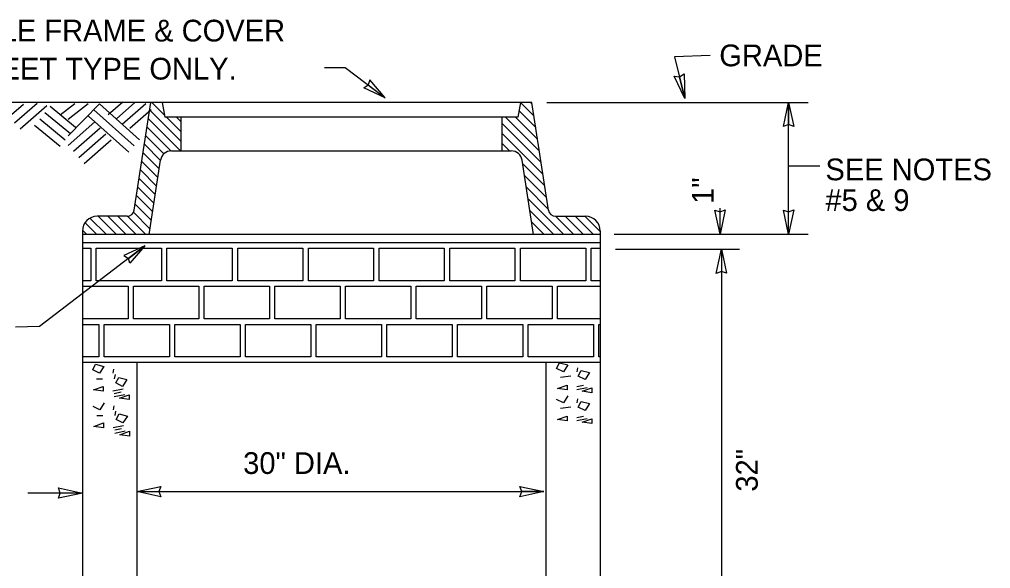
# Model space of a CAD drawing. Extents: x 19188 to 19495, y 20866 to 21061.
# Drawn here: x 19440.07 to 19477.48, y 21039.63 to 21060.79 of the extents above; entities that cross this region are included whole.
import ezdxf

# ---------------------------------------------------------------- set-up
doc = ezdxf.new("R2010")
doc.units = 0
doc.layers.add('G-ANNO-NOTE', color=7, linetype='Continuous')

msp = doc.modelspace()

# ---------------------------------------------------------------- linework, layer by layer
at = {"layer": 'G-ANNO-NOTE'}
for p, q in [((19466.687, 21059.399), (19465.308, 21059.346)), ((19465.308, 21059.346), (19465.711, 21057.746)), ((19451.822, 21058.933), (19452.62, 21058.933)), ((19452.62, 21058.933), (19454.162, 21057.763)), ((19465.711, 21057.746), (19465.503, 21058.573)), ((19445.138, 21057.586), (19431.945, 21057.586)), ((19440.235, 21057.514), (19439.682, 21057.029)), ((19440.75, 21057.549), (19439.889, 21056.793)), ((19441.13, 21057.464), (19440.096, 21056.557)), ((19442.233, 21056.626), (19441.256, 21057.426)), ((19441.64, 21057.106), (19442.212, 21057.549)), ((19441.946, 21056.946), (19442.724, 21057.548)), ((19443.152, 21057.532), (19441.946, 21056.305)), ((19443.152, 21057.532), (19444.704, 21056.145)), ((19444.057, 21057.597), (19443.497, 21057.105)), ((19444.506, 21057.572), (19443.819, 21056.97)), ((19444.946, 21057.54), (19444.028, 21056.735)), ((19444.497, 21053.442), (19445.138, 21057.586)), ((19459.81, 21057.586), (19445.138, 21057.586)), ((19445.179, 21057.585), (19445.654, 21057.11)), ((19445.565, 21057.587), (19445.674, 21057.02)), ((19459.378, 21057.583), (19459.274, 21057.02)), ((19459.377, 21057.584), (19459.89, 21057.071)), ((19459.755, 21057.585), (19459.82, 21057.52)), ((19460.451, 21053.442), (19459.81, 21057.586)), ((19460.394, 21057.586), (19470.452, 21057.586)), ((19469.705, 21052.518), (19469.705, 21057.586)), ((19469.705, 21057.586), (19469.705, 21056.733)), ((19442.034, 21056.383), (19441.057, 21057.183)), ((19442.734, 21057.064), (19444.286, 21055.677)), ((19442.943, 21057.298), (19444.495, 21055.912)), ((19445.153, 21057.303), (19444.327, 21056.579)), ((19445.092, 21057.292), (19446.292, 21056.092)), ((19459.274, 21057.02), (19445.674, 21057.02)), ((19445.744, 21057.021), (19446.292, 21056.472)), ((19446.12, 21057.023), (19446.292, 21056.852)), ((19446.292, 21057.025), (19446.292, 21055.729)), ((19458.656, 21057.025), (19458.656, 21055.729)), ((19458.797, 21057.024), (19460.098, 21055.723)), ((19459.18, 21057.021), (19460.029, 21056.172)), ((19459.32, 21057.261), (19459.96, 21056.621)), ((19441.636, 21055.896), (19440.659, 21056.696)), ((19441.835, 21056.139), (19440.858, 21056.94)), ((19442.98, 21056.839), (19441.946, 21055.932)), ((19444.991, 21056.634), (19445.914, 21055.71)), ((19445.042, 21056.963), (19446.275, 21055.729)), ((19458.656, 21056.785), (19460.168, 21055.273)), ((19443.187, 21056.603), (19442.153, 21055.696)), ((19443.395, 21056.366), (19442.36, 21055.46)), ((19444.94, 21056.304), (19445.63, 21055.615)), ((19458.656, 21056.405), (19460.238, 21054.823)), ((19443.602, 21056.13), (19442.567, 21055.223)), ((19444.889, 21055.976), (19445.508, 21055.356)), ((19458.656, 21056.025), (19458.956, 21055.725)), ((19444.838, 21055.647), (19445.457, 21055.027)), ((19445.929, 21055.724), (19459.019, 21055.724)), ((19444.787, 21055.318), (19445.407, 21054.698)), ((19445.066, 21052.499), (19445.51, 21055.364)), ((19459.882, 21052.499), (19459.438, 21055.364)), ((19459.461, 21055.22), (19460.307, 21054.374)), ((19470.912, 21055.132), (19469.705, 21055.132)), ((19444.736, 21054.989), (19445.356, 21054.369)), ((19459.53, 21054.771), (19460.376, 21053.925)), ((19444.685, 21054.66), (19445.305, 21054.04)), ((19444.583, 21054.002), (19445.203, 21053.382)), ((19444.634, 21054.331), (19445.254, 21053.711)), ((19459.6, 21054.322), (19460.446, 21053.475)), ((19444.533, 21053.673), (19445.152, 21053.053)), ((19459.669, 21053.872), (19461.044, 21052.497)), ((19444.462, 21053.363), (19445.101, 21052.724)), ((19459.739, 21053.423), (19460.663, 21052.498)), ((19467.061, 21052.518), (19467.061, 21053.516)), ((19467.061, 21052.518), (19467.061, 21053.371)), ((19469.705, 21052.518), (19469.705, 21053.371)), ((19442.599, 21052.946), (19443.049, 21052.496)), ((19442.801, 21053.124), (19443.429, 21052.497)), ((19444.217, 21053.203), (19443.065, 21053.203)), ((19443.103, 21053.203), (19443.808, 21052.497)), ((19443.483, 21053.203), (19444.187, 21052.498)), ((19443.863, 21053.203), (19444.567, 21052.499)), ((19444.244, 21053.201), (19444.946, 21052.499)), ((19459.808, 21052.973), (19460.283, 21052.499)), ((19460.717, 21053.204), (19461.424, 21052.497)), ((19460.731, 21053.203), (19461.883, 21053.203)), ((19461.099, 21053.203), (19461.805, 21052.496)), ((19461.479, 21053.203), (19462.185, 21052.496)), ((19461.859, 21053.203), (19462.449, 21052.612)), ((19442.498, 21052.668), (19442.67, 21052.496)), ((19442.5, 21052.637), (19442.5, 21052.496)), ((19442.5, 21052.508), (19442.511, 21052.496)), ((19462.449, 21052.496), (19442.5, 21052.496)), ((19442.5, 21052.496), (19442.5, 21034.451)), ((19459.878, 21052.524), (19459.903, 21052.499)), ((19462.449, 21052.508), (19462.437, 21052.496)), ((19462.449, 21052.637), (19462.449, 21052.496)), ((19462.449, 21052.496), (19462.449, 21034.451)), ((19462.981, 21052.518), (19470.452, 21052.518)), ((19462.449, 21052.181), (19442.5, 21052.181)), ((19463.038, 21051.931), (19467.808, 21051.931)), ((19467.119, 21051.931), (19467.119, 21034.434)), ((19467.119, 21051.931), (19467.119, 21051.079)), ((19462.449, 21047.573), (19442.5, 21047.573)), ((19442.894, 21047.29), (19443.009, 21047.503)), ((19443.152, 21047.156), (19442.894, 21047.29)), ((19443.009, 21047.503), (19443.325, 21047.423)), ((19443.325, 21047.423), (19443.152, 21047.156)), ((19443.698, 21047.316), (19443.67, 21047.156)), ((19444.594, 21047.573), (19444.594, 21034.451)), ((19460.354, 21047.573), (19460.354, 21034.451)), ((19460.768, 21047.343), (19460.883, 21047.556)), ((19461.026, 21047.209), (19460.768, 21047.343)), ((19460.883, 21047.556), (19461.199, 21047.476)), ((19461.199, 21047.476), (19461.026, 21047.209)), ((19461.572, 21047.37), (19461.544, 21047.209)), ((19461.601, 21047.049), (19461.716, 21047.263)), ((19461.716, 21047.263), (19462.032, 21047.183)), ((19443.037, 21046.943), (19443.267, 21046.943)), ((19443.756, 21047.103), (19443.727, 21046.943)), ((19443.785, 21046.783), (19443.899, 21046.996)), ((19443.899, 21046.996), (19444.216, 21046.916)), ((19444.216, 21046.916), (19444.043, 21046.65)), ((19461.314, 21047.049), (19460.912, 21046.996)), ((19461.86, 21046.916), (19461.601, 21047.049)), ((19462.032, 21047.183), (19461.86, 21046.916)), ((19442.923, 21046.516), (19443.296, 21046.65)), ((19443.296, 21046.462), (19442.923, 21046.516)), ((19443.296, 21046.65), (19443.296, 21046.462)), ((19444.072, 21046.543), (19443.67, 21046.462)), ((19444.043, 21046.65), (19443.785, 21046.783)), ((19460.797, 21046.57), (19461.17, 21046.703)), ((19461.17, 21046.516), (19460.797, 21046.57)), ((19461.17, 21046.703), (19461.17, 21046.516)), ((19461.544, 21046.65), (19461.802, 21046.703)), ((19461.946, 21046.596), (19461.544, 21046.516)), ((19461.745, 21046.462), (19462.119, 21046.596)), ((19462.119, 21046.596), (19462.119, 21046.409)), ((19443.727, 21046.383), (19443.986, 21046.436)), ((19444.129, 21046.329), (19443.727, 21046.249)), ((19443.928, 21046.196), (19444.302, 21046.329)), ((19444.302, 21046.142), (19443.928, 21046.196)), ((19444.302, 21046.329), (19444.302, 21046.142)), ((19461.026, 21046.015), (19460.768, 21046.149)), ((19461.199, 21046.282), (19461.026, 21046.015)), ((19461.572, 21046.175), (19461.544, 21046.015)), ((19462.119, 21046.409), (19461.745, 21046.462)), ((19443.167, 21045.747), (19442.909, 21045.881)), ((19443.34, 21046.014), (19443.167, 21045.747)), ((19443.713, 21045.908), (19443.685, 21045.747)), ((19461.314, 21045.855), (19460.912, 21045.802)), ((19461.601, 21045.855), (19461.716, 21046.069)), ((19461.86, 21045.722), (19461.601, 21045.855)), ((19461.716, 21046.069), (19462.032, 21045.989)), ((19462.032, 21045.989), (19461.86, 21045.722)), ((19443.053, 21045.534), (19443.282, 21045.534)), ((19443.771, 21045.694), (19443.742, 21045.534)), ((19443.8, 21045.374), (19443.915, 21045.588)), ((19443.915, 21045.588), (19444.231, 21045.508)), ((19444.231, 21045.508), (19444.058, 21045.241)), ((19460.797, 21045.375), (19461.17, 21045.508)), ((19461.17, 21045.508), (19461.17, 21045.322)), ((19461.544, 21045.455), (19461.802, 21045.508)), ((19461.946, 21045.402), (19461.544, 21045.322)), ((19461.745, 21045.269), (19462.119, 21045.402)), ((19462.119, 21045.402), (19462.119, 21045.215)), ((19442.937, 21045.107), (19443.311, 21045.241)), ((19443.311, 21045.054), (19442.937, 21045.107)), ((19443.311, 21045.241), (19443.311, 21045.054)), ((19444.087, 21045.134), (19443.685, 21045.054)), ((19443.742, 21044.974), (19444.001, 21045.027)), ((19444.058, 21045.241), (19443.8, 21045.374)), ((19461.17, 21045.322), (19460.797, 21045.375)), ((19462.119, 21045.215), (19461.745, 21045.269)), ((19444.144, 21044.921), (19443.742, 21044.841)), ((19443.944, 21044.788), (19444.317, 21044.921)), ((19444.317, 21044.734), (19443.944, 21044.788)), ((19444.317, 21044.921), (19444.317, 21044.734)), ((19442.5, 21042.542), (19440.394, 21042.542)), ((19442.5, 21042.542), (19441.646, 21042.542)), ((19444.594, 21042.596), (19460.279, 21042.596)), ((19444.594, 21042.596), (19445.447, 21042.596)), ((19460.279, 21042.596), (19459.427, 21042.596))]:
    msp.add_line(p, q, dxfattribs=at)
for points in [[(19465.503, 21058.573), (19465.682, 21058.695), (19465.711, 21057.746), (19465.296, 21058.596), (19465.503, 21058.573)], [(19469.705, 21056.733), (19469.501, 21056.658), (19469.705, 21057.586), (19469.9, 21056.66), (19469.705, 21056.733)], [(19467.061, 21053.371), (19467.265, 21053.446), (19467.061, 21052.518), (19466.867, 21053.444), (19467.061, 21053.371)], [(19469.705, 21053.371), (19469.909, 21053.446), (19469.705, 21052.518), (19469.51, 21053.444), (19469.705, 21053.371)], [(19444.907, 21052.068), (19440.852, 21048.956), (19439.916, 21048.938)], [(19442.5, 21051.972), (19442.825, 21051.972), (19442.825, 21050.715), (19442.5, 21050.715)], [(19462.449, 21050.715), (19462.095, 21050.715), (19462.095, 21051.972), (19462.449, 21051.972)], [(19467.119, 21051.078), (19466.915, 21051.004), (19467.119, 21051.931), (19467.313, 21051.006), (19467.119, 21051.078)], [(19442.5, 21050.506), (19444.259, 21050.506), (19444.259, 21049.249), (19442.5, 21049.249)], [(19462.449, 21049.249), (19460.806, 21049.249), (19460.806, 21050.506), (19462.449, 21050.506)], [(19442.5, 21049.039), (19443.128, 21049.039), (19443.128, 21047.783), (19442.5, 21047.783)], [(19462.449, 21047.783), (19462.399, 21047.783), (19462.399, 21049.039), (19462.449, 21049.039)], [(19445.447, 21042.596), (19445.521, 21042.392), (19444.594, 21042.596), (19445.519, 21042.79), (19445.447, 21042.596)], [(19459.426, 21042.596), (19459.352, 21042.799), (19460.279, 21042.596), (19459.354, 21042.401), (19459.426, 21042.596)], [(19441.646, 21042.542), (19441.572, 21042.746), (19442.5, 21042.542), (19441.573, 21042.348), (19441.646, 21042.542)]]:
    msp.add_lwpolyline(points, dxfattribs=at)
for points in [[(19453.566, 21058.463), (19453.505, 21058.262), (19454.162, 21057.763), (19453.335, 21058.154), (19453.505, 21058.262), (19454.162, 21057.763)], [(19443.035, 21051.972), (19445.548, 21051.972), (19445.548, 21050.715), (19443.035, 21050.715)], [(19444.1, 21051.69), (19444.272, 21051.581), (19444.907, 21052.068), (19444.329, 21051.394), (19444.272, 21051.581), (19444.907, 21052.068)], [(19445.757, 21051.972), (19448.271, 21051.972), (19448.271, 21050.715), (19445.757, 21050.715)], [(19448.48, 21051.972), (19450.994, 21051.972), (19450.994, 21050.715), (19448.48, 21050.715)], [(19451.203, 21051.972), (19453.717, 21051.972), (19453.717, 21050.715), (19451.203, 21050.715)], [(19453.926, 21051.972), (19456.44, 21051.972), (19456.44, 21050.715), (19453.926, 21050.715)], [(19456.65, 21051.972), (19459.163, 21051.972), (19459.163, 21050.715), (19456.65, 21050.715)], [(19459.373, 21051.972), (19461.886, 21051.972), (19461.886, 21050.715), (19459.373, 21050.715)], [(19444.468, 21050.506), (19446.982, 21050.506), (19446.982, 21049.249), (19444.468, 21049.249)], [(19447.192, 21050.506), (19449.705, 21050.506), (19449.705, 21049.249), (19447.192, 21049.249)], [(19449.915, 21050.506), (19452.428, 21050.506), (19452.428, 21049.249), (19449.915, 21049.249)], [(19452.638, 21050.506), (19455.151, 21050.506), (19455.151, 21049.249), (19452.638, 21049.249)], [(19455.361, 21050.506), (19457.874, 21050.506), (19457.874, 21049.249), (19455.361, 21049.249)], [(19458.083, 21050.506), (19460.597, 21050.506), (19460.597, 21049.249), (19458.083, 21049.249)], [(19443.337, 21049.039), (19445.851, 21049.039), (19445.851, 21047.783), (19443.337, 21047.783)], [(19446.06, 21049.039), (19448.574, 21049.039), (19448.574, 21047.783), (19446.06, 21047.783)], [(19448.783, 21049.039), (19451.297, 21049.039), (19451.297, 21047.783), (19448.783, 21047.783)], [(19451.506, 21049.039), (19454.02, 21049.039), (19454.02, 21047.783), (19451.506, 21047.783)], [(19454.229, 21049.039), (19456.743, 21049.039), (19456.743, 21047.783), (19454.229, 21047.783)], [(19456.952, 21049.039), (19459.466, 21049.039), (19459.466, 21047.783), (19456.952, 21047.783)], [(19459.675, 21049.039), (19462.189, 21049.039), (19462.189, 21047.783), (19459.675, 21047.783)]]:
    msp.add_lwpolyline(points, close=True, dxfattribs=at)
for centre, radius, start, end in [((19445.929, 21055.299), 0.424, 90, 171.2067), ((19459.019, 21055.299), 0.424, 8.7933, 90), ((19444.218, 21053.485), 0.283, 270, 351.2062), ((19460.731, 21053.485), 0.283, 188.7938, 270), ((19443.065, 21052.637), 0.566, 90, 180), ((19461.883, 21052.637), 0.566, 0, 90)]:
    msp.add_arc(centre, radius, start, end, dxfattribs=at)

# ---------------------------------------------------------------- texts
for s, height, p in [('HANDHOLE FRAME & COVER', 0.83785, (19434.494, 21059.936)), ('GRADE ', 0.8379, (19467.033, 21058.981)), ('USE STREET TYPE ONLY.', 0.83785, (19434.494, 21058.47)), ('SEE NOTES', 0.8379, (19471.122, 21054.59)), ('#5 & 9', 0.8379, (19471.122, 21053.407)), ('30" DIA.', 0.8379, (19448.692, 21043.278))]:
    msp.add_text(s, height=height, dxfattribs=at).set_placement(p)
for s, p in [('1"', (19466.82, 21053.678)), ('32"', (19468.514, 21042.596))]:
    msp.add_text(s, height=0.8379, rotation=90, dxfattribs=at).set_placement(p)

doc.saveas('drawing.dxf')
